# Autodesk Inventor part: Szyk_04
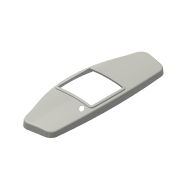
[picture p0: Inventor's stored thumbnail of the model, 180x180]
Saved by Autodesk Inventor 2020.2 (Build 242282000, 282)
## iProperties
Created: 2005-06
Part Number: Szyk_04
Document SubType Name: Modeling
Designer: F.Stasiak
Manufacturer: Standard
Standards Organization: Custom
Density: 1 g/cm^3
Material: Ogólny
Appearance: Gładkie — w kolorze kości słoniowej
Manager: www.cadconsulting.pl
Company: Fabian Stasiak CAD Consulting
Author: F.Stasiak
Subject: Zbiór ćwiczeń. Autodesk Inventor 2020. Kurs podstawowy
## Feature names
1. Wyciągnięcie proste1 [Extrusion]
2. Zaokrąglenie1 [Fillet]
3. Zaokrąglenie2 [Fillet]
4. Skorupa1
5. Wyciągnięcie proste2 [Extrusion]
6. Zaokrąglenie3 [Fillet]
7. Zaokrąglenie4 [Fillet]
8. Wyciągnięcie proste5 [Extrusion]
9. Otwór pod klawisz [Extrusion]
## Parameters: d2 = 20 deg, d6 = 25 mm, d7 = 35 mm, d9 = -5 deg, d13 = 0, d14 = 2 mm, d15 = 0.5 mm, d16 = 12 mm, d17 = 1.5 mm, d18 = 1.5 mm, d19 = 25 mm, d20 = 25 mm, d22 = 0, d23 = 4 mm, d24 = 1.5 mm, d25 = 3 mm, d26 = 1 mm, d27 = 15 mm, d28 = 5 mm, d29 = 2.5 mm, d30 = 31 mm, d31 = 13 mm, d33 = 0, d43 = 0, d50 = 0
